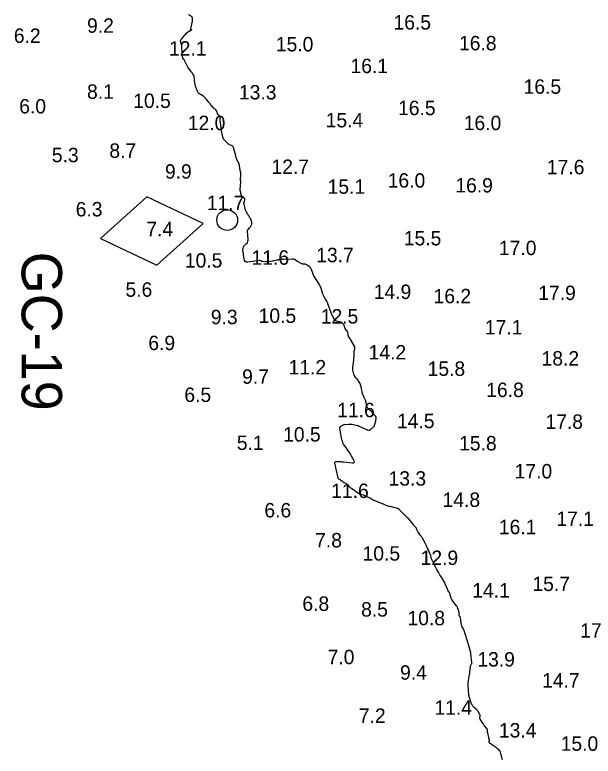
# Model space of a CAD drawing. Extents: x 815352 to 820877, y 582403 to 597439.
# Drawn here: x 819576.6 to 819777.2, y 593041.8 to 593298.9 of the extents above; entities that cross this region are included whole.
import ezdxf

# ---------------------------------------------------------------- set-up
doc = ezdxf.new("R2010")
doc.units = 0
for name, color, linetype in [('V-CHAN-NAID', 7, 'Continuous'), ('V-CONT-EL12', 7, 'Continuous'), ('V-TOPO-SOUN', 7, 'Continuous')]:
    doc.layers.add(name, color=color, linetype=linetype)

msp = doc.modelspace()

# ---------------------------------------------------------------- linework, layer by layer
at = {"layer": 'V-CHAN-NAID'}
msp.add_lwpolyline([(819641.95, 593226.5), (819622.41, 593235.79), (819606.32, 593221.33), (819625.86, 593212.04)], close=True, dxfattribs=at)
msp.add_circle((819650.26, 593227.71), 3.6, dxfattribs=at)
at = {"layer": 'V-CONT-EL12'}
for points in [[(819639.18, 593274.47), (819639.14, 593274.68), (819638.99, 593275.53), (819638.96, 593275.74), (819638.93, 593275.95), (819638.9, 593276.16), (819638.89, 593276.38), (819638.79, 593277.58), (819638.77, 593277.69), (819638.74, 593277.8), (819638.69, 593277.9), (819638.64, 593278), (819638.36, 593278.4), (819638.3, 593278.49), (819638.23, 593278.58), (819638.16, 593278.66), (819638.09, 593278.75), (819637.79, 593279.07), (819637.72, 593279.16), (819637.65, 593279.24), (819637.59, 593279.33), (819637.52, 593279.42), (819636.64, 593280.76), (819636.5, 593280.98), (819636.36, 593281.21), (819636.24, 593281.44), (819636.12, 593281.68), (819635.59, 593282.83), (819635.52, 593282.97), (819635.44, 593283.11), (819635.36, 593283.25), (819635.27, 593283.38), (819634.91, 593283.9), (819634.83, 593284.04), (819634.77, 593284.18), (819634.73, 593284.33), (819634.71, 593284.49), (819634.57, 593287.44), (819634.56, 593287.69), (819634.52, 593287.95), (819634.48, 593288.2), (819634.42, 593288.46), (819634.11, 593289.72), (819634.09, 593289.84), (819634.1, 593289.95), (819634.13, 593290.06), (819634.19, 593290.16), (819634.47, 593290.55), (819634.55, 593290.65), (819634.62, 593290.75), (819634.7, 593290.84), (819634.78, 593290.93), (819636.29, 593292.61), (819636.39, 593292.72), (819636.49, 593292.81), (819636.61, 593292.9), (819636.72, 593292.98), (819637.21, 593293.29), (819637.34, 593293.37), (819637.47, 593293.43), (819637.6, 593293.49), (819637.74, 593293.54), (819637.98, 593293.62), (819637.76, 593293.58), (819637.62, 593293.63), (819637.56, 593293.76), (819637.59, 593293.98), (819638.22, 593296.67), (819638.24, 593296.8), (819638.26, 593296.93), (819638.26, 593297.06), (819638.26, 593297.2), (819638.21, 593297.73), (819638.18, 593297.86), (819638.13, 593297.98), (819638.06, 593298.07), (819637.96, 593298.16), (819637.27, 593298.65), (819637.13, 593298.76), (819636.98, 593298.88), (819636.85, 593299)], [(819745.76, 593040.61), (819745.35, 593042.17), (819745.32, 593042.29), (819745.28, 593042.41), (819745.25, 593042.53), (819745.22, 593042.64), (819745.06, 593043.23), (819745.04, 593043.29), (819745.01, 593043.35), (819744.98, 593043.41), (819744.94, 593043.47), (819744.79, 593043.69), (819744.75, 593043.74), (819744.71, 593043.79), (819744.66, 593043.84), (819744.62, 593043.89), (819743.94, 593044.55), (819743.81, 593044.67), (819743.67, 593044.78), (819743.53, 593044.89), (819743.38, 593044.99), (819741.99, 593045.93), (819741.93, 593045.96), (819741.88, 593046), (819741.82, 593046.03), (819741.77, 593046.06), (819741.54, 593046.19), (819741.48, 593046.23), (819741.43, 593046.27), (819741.39, 593046.31), (819741.34, 593046.35), (819741.17, 593046.54), (819741.13, 593046.59), (819741.11, 593046.64), (819741.1, 593046.69), (819741.1, 593046.76), (819741.19, 593047.31), (819741.21, 593047.43), (819741.21, 593047.54), (819741.2, 593047.65), (819741.17, 593047.77), (819740.63, 593049.97), (819740.6, 593050.09), (819740.58, 593050.21), (819740.57, 593050.33), (819740.56, 593050.46), (819740.53, 593050.95), (819740.51, 593051.07), (819740.48, 593051.19), (819740.43, 593051.29), (819740.36, 593051.39), (819739.58, 593052.3), (819739.43, 593052.49), (819739.28, 593052.68), (819739.15, 593052.88), (819739.02, 593053.08), (819738.04, 593054.64), (819737.98, 593054.76), (819737.94, 593054.89), (819737.93, 593055.02), (819737.93, 593055.15), (819738.01, 593055.7), (819738.02, 593055.84), (819738.01, 593055.97), (819737.98, 593056.09), (819737.93, 593056.22), (819737.68, 593056.71), (819737.61, 593056.83), (819737.54, 593056.95), (819737.47, 593057.06), (819737.39, 593057.18), (819737.01, 593057.73), (819736.91, 593057.85), (819736.81, 593057.97), (819736.7, 593058.08), (819736.58, 593058.19), (819735.78, 593058.85), (819735.7, 593058.93), (819735.62, 593059.01), (819735.55, 593059.1), (819735.48, 593059.2), (819735.24, 593059.6), (819735.18, 593059.7), (819735.13, 593059.8), (819735.08, 593059.91), (819735.04, 593060.02), (819734.41, 593061.79), (819734.31, 593062.12), (819734.22, 593062.46), (819734.16, 593062.8), (819734.12, 593063.15), (819733.87, 593066.31), (819733.87, 593066.37), (819733.87, 593066.43), (819733.87, 593066.49), (819733.87, 593066.55), (819733.88, 593066.8), (819733.88, 593066.86), (819733.88, 593066.91), (819733.88, 593066.96), (819733.87, 593067.01), (819733.84, 593067.22), (819733.83, 593067.27), (819733.83, 593067.33), (819733.83, 593067.38), (819733.84, 593067.43), (819734.36, 593070.17), (819734.37, 593070.22), (819734.38, 593070.28), (819734.38, 593070.33), (819734.39, 593070.39), (819734.4, 593070.61), (819734.41, 593070.66), (819734.41, 593070.72), (819734.42, 593070.77), (819734.42, 593070.83), (819734.64, 593072.86), (819734.66, 593072.99), (819734.69, 593073.12), (819734.74, 593073.24), (819734.79, 593073.37), (819735.04, 593073.85), (819735.09, 593073.97), (819735.12, 593074.1), (819735.14, 593074.23), (819735.13, 593074.36), (819734.84, 593077.34), (819734.83, 593077.37), (819734.83, 593077.41), (819734.82, 593077.44), (819734.81, 593077.47), (819734.79, 593077.6), (819734.78, 593077.63), (819734.77, 593077.67), (819734.76, 593077.7), (819734.76, 593077.73), (819734.64, 593078.18), (819734.62, 593078.27), (819734.6, 593078.35), (819734.57, 593078.44), (819734.55, 593078.52), (819733.93, 593080.57), (819733.85, 593080.85), (819733.77, 593081.12), (819733.69, 593081.39), (819733.61, 593081.67), (819733.29, 593082.76), (819733.21, 593083.04), (819733.13, 593083.31), (819733.04, 593083.58), (819732.95, 593083.85), (819732.43, 593085.42), (819732.39, 593085.56), (819732.33, 593085.69), (819732.27, 593085.82), (819732.2, 593085.95), (819731.9, 593086.44), (819731.83, 593086.57), (819731.77, 593086.7), (819731.72, 593086.83), (819731.68, 593086.97), (819731.54, 593087.55), (819731.51, 593087.69), (819731.48, 593087.83), (819731.45, 593087.98), (819731.43, 593088.12), (819731.17, 593089.91), (819731.15, 593089.99), (819731.13, 593090.06), (819731.1, 593090.12), (819731.06, 593090.19), (819730.88, 593090.43), (819730.84, 593090.5), (819730.81, 593090.56), (819730.79, 593090.63), (819730.78, 593090.71), (819730.68, 593091.71), (819730.65, 593091.9), (819730.62, 593092.08), (819730.57, 593092.27), (819730.51, 593092.45), (819730.21, 593093.27), (819730.14, 593093.46), (819730.04, 593093.64), (819729.94, 593093.82), (819729.82, 593093.99), (819728.56, 593095.59), (819728.38, 593095.84), (819728.23, 593096.11), (819728.1, 593096.38), (819728, 593096.67), (819727.53, 593098.26), (819727.49, 593098.35), (819727.45, 593098.43), (819727.4, 593098.51), (819727.34, 593098.58), (819727.08, 593098.86), (819727.01, 593098.93), (819726.96, 593099.01), (819726.91, 593099.09), (819726.87, 593099.18), (819725.75, 593101.82), (819725.59, 593102.18), (819725.42, 593102.53), (819725.24, 593102.86), (819725.04, 593103.2), (819724.07, 593104.73), (819723.93, 593104.95), (819723.8, 593105.17), (819723.67, 593105.39), (819723.54, 593105.62), (819723.03, 593106.54), (819722.91, 593106.76), (819722.8, 593106.97), (819722.69, 593107.19), (819722.57, 593107.4), (819722.13, 593108.27), (819722.02, 593108.49), (819721.92, 593108.71), (819721.81, 593108.93), (819721.71, 593109.15), (819721.17, 593110.3), (819721.12, 593110.4), (819721.08, 593110.51), (819721.05, 593110.62), (819721.03, 593110.73), (819720.94, 593111.17), (819720.91, 593111.28), (819720.88, 593111.39), (819720.85, 593111.5), (819720.81, 593111.6), (819720.38, 593112.63), (819720.32, 593112.76), (819720.27, 593112.89), (819720.22, 593113.02), (819720.16, 593113.15), (819719.92, 593113.74), (819719.88, 593113.83), (819719.84, 593113.92), (819719.79, 593114), (819719.75, 593114.09), (819719.54, 593114.42), (819719.49, 593114.51), (819719.44, 593114.59), (819719.4, 593114.68), (819719.36, 593114.77), (819718.94, 593115.7), (819718.85, 593115.88), (819718.76, 593116.07), (819718.67, 593116.24), (819718.57, 593116.42), (819718.03, 593117.37), (819717.9, 593117.58), (819717.77, 593117.79), (819717.63, 593118), (819717.48, 593118.2), (819716.5, 593119.53), (819716.4, 593119.67), (819716.32, 593119.81), (819716.25, 593119.95), (819716.19, 593120.1), (819715.96, 593120.72), (819715.89, 593120.87), (819715.82, 593121.01), (819715.72, 593121.14), (819715.62, 593121.26), (819715.16, 593121.74), (819715.05, 593121.86), (819714.94, 593121.98), (819714.83, 593122.1), (819714.73, 593122.23), (819713.26, 593124.11), (819713.2, 593124.19), (819713.13, 593124.25), (819713.05, 593124.32), (819712.97, 593124.37), (819712.6, 593124.6), (819712.54, 593124.65), (819712.48, 593124.69), (819712.43, 593124.75), (819712.39, 593124.81), (819712.22, 593125.05), (819712.18, 593125.11), (819712.13, 593125.17), (819712.08, 593125.23), (819712.03, 593125.28), (819710.2, 593127.13), (819709.92, 593127.38), (819709.62, 593127.58), (819709.29, 593127.74), (819708.94, 593127.85), (819706.84, 593128.39), (819706.8, 593128.4), (819706.75, 593128.4), (819706.71, 593128.41), (819706.66, 593128.4), (819706.47, 593128.39), (819706.42, 593128.39), (819706.38, 593128.4), (819706.33, 593128.41), (819706.29, 593128.42), (819705.15, 593128.91), (819704.94, 593128.99), (819704.74, 593129.08), (819704.53, 593129.17), (819704.32, 593129.25), (819701.23, 593130.52), (819701.17, 593130.54), (819701.11, 593130.57), (819701.05, 593130.59), (819700.99, 593130.62), (819700.69, 593130.74), (819700.66, 593130.76), (819700.62, 593130.77), (819700.58, 593130.79), (819700.54, 593130.81), (819700.38, 593130.89), (819700.35, 593130.91), (819700.31, 593130.93), (819700.28, 593130.95), (819700.24, 593130.98), (819700.1, 593131.11), (819700.06, 593131.13), (819700.02, 593131.16), (819699.98, 593131.18), (819699.94, 593131.21), (819698.55, 593131.88), (819698.3, 593131.99), (819698.05, 593132.1), (819697.79, 593132.2), (819697.53, 593132.29), (819696.25, 593132.7), (819696.09, 593132.76), (819695.94, 593132.83), (819695.79, 593132.91), (819695.65, 593133), (819695.09, 593133.39), (819694.95, 593133.49), (819694.81, 593133.59), (819694.68, 593133.69), (819694.54, 593133.79), (819693.34, 593134.63), (819693.2, 593134.74), (819693.06, 593134.86), (819692.93, 593135), (819692.81, 593135.13), (819692.34, 593135.71), (819692.21, 593135.85), (819692.08, 593135.97), (819691.93, 593136.07), (819691.77, 593136.16), (819690.9, 593136.58), (819690.76, 593136.65), (819690.63, 593136.73), (819690.5, 593136.81), (819690.38, 593136.9), (819689.86, 593137.32), (819689.76, 593137.4), (819689.65, 593137.48), (819689.55, 593137.56), (819689.44, 593137.64), (819688.99, 593137.93), (819688.89, 593138.01), (819688.81, 593138.1), (819688.75, 593138.21), (819688.71, 593138.33), (819687.62, 593143.41), (819687.61, 593143.69), (819687.68, 593143.88), (819687.86, 593143.99), (819688.13, 593144.01), (819689.41, 593143.96), (819689.73, 593143.95), (819690.05, 593143.93), (819690.37, 593143.9), (819690.69, 593143.87), (819693.76, 593143.52), (819694.14, 593143.53), (819694.35, 593143.65), (819694.39, 593143.89), (819694.26, 593144.25), (819693.43, 593145.9), (819693.21, 593146.31), (819692.98, 593146.71), (819692.73, 593147.1), (819692.46, 593147.48), (819690.96, 593149.51), (819690.65, 593149.99), (819690.4, 593150.49), (819690.21, 593151.02), (819690.08, 593151.57), (819689.36, 593155.58), (819689.35, 593155.76), (819689.39, 593155.93), (819689.48, 593156.06), (819689.62, 593156.18), (819690.29, 593156.6), (819690.46, 593156.7), (819690.64, 593156.77), (819690.82, 593156.82), (819691.02, 593156.85), (819692.36, 593156.97), (819692.65, 593156.98), (819692.94, 593156.98), (819693.22, 593156.95), (819693.51, 593156.91), (819695.01, 593156.61), (819695.35, 593156.54), (819695.68, 593156.44), (819696.01, 593156.31), (819696.33, 593156.17), (819698.39, 593155.18), (819698.51, 593155.13), (819698.63, 593155.09), (819698.75, 593155.05), (819698.87, 593155.02), (819699.38, 593154.92), (819699.5, 593154.91), (819699.62, 593154.92), (819699.73, 593154.96), (819699.83, 593155.03), (819701.02, 593156.01), (819701.14, 593156.13), (819701.25, 593156.26), (819701.33, 593156.4), (819701.39, 593156.56), (819701.65, 593157.43), (819701.67, 593157.5), (819701.69, 593157.56), (819701.71, 593157.63), (819701.73, 593157.7), (819701.82, 593157.96), (819701.84, 593158.03), (819701.86, 593158.09), (819701.87, 593158.16), (819701.88, 593158.23), (819701.96, 593159.06), (819701.96, 593159.22), (819701.94, 593159.37), (819701.88, 593159.5), (819701.78, 593159.63), (819700.57, 593161.04), (819700.41, 593161.22), (819700.25, 593161.39), (819700.08, 593161.56), (819699.91, 593161.72), (819699.17, 593162.4), (819699.03, 593162.55), (819698.91, 593162.72), (819698.82, 593162.91), (819698.76, 593163.11), (819698.5, 593164.19), (819698.48, 593164.27), (819698.46, 593164.36), (819698.44, 593164.45), (819698.43, 593164.54), (819698.37, 593164.9), (819698.35, 593164.99), (819698.32, 593165.08), (819698.29, 593165.16), (819698.25, 593165.24), (819697.9, 593165.91), (819697.83, 593166.05), (819697.77, 593166.19), (819697.7, 593166.34), (819697.64, 593166.48), (819697.12, 593167.76), (819697.11, 593167.79), (819697.1, 593167.81), (819697.1, 593167.84), (819697.09, 593167.86), (819697.08, 593167.97), (819697.08, 593167.99), (819697.08, 593168.02), (819697.07, 593168.04), (819697.07, 593168.07), (819696.81, 593169.39), (819696.78, 593169.53), (819696.75, 593169.67), (819696.72, 593169.8), (819696.69, 593169.94), (819696.56, 593170.49), (819696.53, 593170.63), (819696.48, 593170.76), (819696.42, 593170.88), (819696.35, 593171.01), (819695.36, 593172.65), (819695.33, 593172.69), (819695.29, 593172.73), (819695.25, 593172.77), (819695.21, 593172.8), (819695.03, 593172.91), (819694.98, 593172.94), (819694.94, 593172.97), (819694.91, 593173.01), (819694.87, 593173.06), (819694.46, 593173.71), (819694.39, 593173.84), (819694.33, 593173.97), (819694.28, 593174.11), (819694.24, 593174.25), (819693.89, 593175.7), (819693.83, 593175.99), (819693.8, 593176.28), (819693.81, 593176.57), (819693.84, 593176.86), (819694.03, 593178.09), (819694.07, 593178.37), (819694.11, 593178.66), (819694.15, 593178.94), (819694.18, 593179.23), (819694.33, 593180.62), (819694.34, 593180.78), (819694.35, 593180.94), (819694.35, 593181.09), (819694.35, 593181.25), (819694.31, 593181.94), (819694.31, 593182.07), (819694.32, 593182.2), (819694.34, 593182.32), (819694.37, 593182.45), (819694.55, 593183.1), (819694.56, 593183.15), (819694.57, 593183.2), (819694.58, 593183.25), (819694.58, 593183.31), (819694.57, 593183.52), (819694.56, 593183.57), (819694.55, 593183.62), (819694.54, 593183.67), (819694.51, 593183.72), (819693.32, 593185.94), (819693.23, 593186.1), (819693.13, 593186.26), (819693.03, 593186.42), (819692.92, 593186.58), (819692.47, 593187.19), (819692.37, 593187.35), (819692.29, 593187.52), (819692.23, 593187.69), (819692.2, 593187.88), (819692.06, 593188.83), (819692.03, 593188.95), (819691.98, 593189.05), (819691.92, 593189.15), (819691.84, 593189.23), (819691.47, 593189.55), (819691.39, 593189.64), (819691.32, 593189.73), (819691.26, 593189.84), (819691.22, 593189.95), (819690.86, 593191.14), (819690.81, 593191.27), (819690.74, 593191.4), (819690.66, 593191.52), (819690.56, 593191.62), (819690.13, 593192.03), (819690.02, 593192.13), (819689.9, 593192.2), (819689.77, 593192.26), (819689.63, 593192.31), (819688.17, 593192.66), (819687.9, 593192.75), (819687.67, 593192.9), (819687.48, 593193.1), (819687.34, 593193.34), (819686.64, 593194.84), (819686.49, 593195.18), (819686.35, 593195.53), (819686.21, 593195.88), (819686.08, 593196.23), (819685.23, 593198.67), (819685.14, 593198.9), (819685.05, 593199.12), (819684.94, 593199.33), (819684.81, 593199.54), (819684.24, 593200.48), (819684.15, 593200.63), (819684.06, 593200.79), (819683.97, 593200.95), (819683.89, 593201.11), (819683.58, 593201.75), (819683.51, 593201.91), (819683.44, 593202.07), (819683.38, 593202.24), (819683.32, 593202.41), (819682.81, 593204.09), (819682.7, 593204.43), (819682.57, 593204.75), (819682.41, 593205.06), (819682.23, 593205.36), (819680.5, 593208.07), (819680.33, 593208.36), (819680.18, 593208.66), (819680.04, 593208.96), (819679.92, 593209.28), (819679.38, 593210.83), (819679.31, 593211), (819679.21, 593211.15), (819679.09, 593211.29), (819678.96, 593211.41), (819678.21, 593211.98), (819678.13, 593212.03), (819678.05, 593212.08), (819677.97, 593212.12), (819677.89, 593212.16), (819677.55, 593212.31), (819677.46, 593212.34), (819677.37, 593212.37), (819677.28, 593212.38), (819677.19, 593212.39), (819676.61, 593212.42), (819676.49, 593212.43), (819676.37, 593212.45), (819676.25, 593212.49), (819676.14, 593212.55), (819674.89, 593213.23), (819674.77, 593213.3), (819674.65, 593213.37), (819674.53, 593213.44), (819674.42, 593213.51), (819673.81, 593213.9), (819673.77, 593213.93), (819673.73, 593213.95), (819673.69, 593213.97), (819673.64, 593214), (819673.47, 593214.08), (819673.42, 593214.1), (819673.38, 593214.11), (819673.33, 593214.13), (819673.28, 593214.14), (819673.02, 593214.19), (819672.96, 593214.2), (819672.9, 593214.21), (819672.84, 593214.21), (819672.78, 593214.21), (819669.78, 593214.09), (819669.64, 593214.08), (819669.49, 593214.08), (819669.35, 593214.07), (819669.21, 593214.05), (819668.54, 593213.99), (819668.45, 593213.98), (819668.35, 593213.97), (819668.26, 593213.95), (819668.17, 593213.94), (819667.8, 593213.88), (819667.7, 593213.87), (819667.61, 593213.85), (819667.52, 593213.83), (819667.43, 593213.81), (819666.6, 593213.61), (819666.43, 593213.57), (819666.27, 593213.54), (819666.1, 593213.51), (819665.93, 593213.49), (819664.41, 593213.29), (819664.21, 593213.27), (819664.02, 593213.26), (819663.82, 593213.26), (819663.62, 593213.27), (819662.62, 593213.34), (819662.52, 593213.35), (819662.42, 593213.37), (819662.32, 593213.39), (819662.22, 593213.43), (819661.84, 593213.59), (819661.75, 593213.63), (819661.65, 593213.65), (819661.55, 593213.66), (819661.45, 593213.65), (819657.41, 593213.12), (819656.88, 593213.13), (819656.49, 593213.3), (819656.23, 593213.64), (819656.1, 593214.15), (819655.73, 593217.48), (819655.72, 593217.59), (819655.72, 593217.7), (819655.74, 593217.8), (819655.76, 593217.91), (819655.87, 593218.34), (819655.91, 593218.44), (819655.95, 593218.54), (819656.01, 593218.63), (819656.08, 593218.72), (819656.72, 593219.38), (819656.77, 593219.43), (819656.83, 593219.47), (819656.88, 593219.51), (819656.95, 593219.55), (819657.2, 593219.68), (819657.25, 593219.71), (819657.3, 593219.76), (819657.33, 593219.81), (819657.35, 593219.88), (819657.46, 593220.48), (819657.48, 593220.61), (819657.49, 593220.73), (819657.49, 593220.86), (819657.49, 593220.98), (819657.3, 593223.88), (819657.31, 593224.05), (819657.35, 593224.21), (819657.42, 593224.35), (819657.53, 593224.48), (819658.02, 593224.99), (819658.13, 593225.12), (819658.24, 593225.26), (819658.33, 593225.4), (819658.41, 593225.56), (819658.75, 593226.3), (819658.81, 593226.48), (819658.84, 593226.65), (819658.83, 593226.84), (819658.8, 593227.02), (819658.5, 593228.03), (819658.48, 593228.08), (819658.46, 593228.12), (819658.43, 593228.17), (819658.4, 593228.2), (819658.26, 593228.35), (819658.23, 593228.39), (819658.2, 593228.43), (819658.17, 593228.47), (819658.14, 593228.51), (819657.74, 593229.13), (819657.66, 593229.25), (819657.59, 593229.37), (819657.52, 593229.49), (819657.45, 593229.61), (819656.82, 593230.73), (819656.71, 593230.96), (819656.6, 593231.19), (819656.52, 593231.44), (819656.45, 593231.69), (819656.1, 593233.23), (819656.07, 593233.42), (819656.06, 593233.61), (819656.08, 593233.79), (819656.12, 593233.98), (819656.33, 593234.73), (819656.36, 593234.91), (819656.34, 593235.07), (819656.27, 593235.22), (819656.14, 593235.35), (819655.45, 593235.92), (819655.34, 593236.03), (819655.24, 593236.16), (819655.17, 593236.31), (819655.13, 593236.46), (819654.96, 593237.27), (819654.94, 593237.36), (819654.92, 593237.45), (819654.9, 593237.54), (819654.88, 593237.63), (819654.79, 593237.99), (819654.78, 593238.08), (819654.77, 593238.17), (819654.76, 593238.26), (819654.77, 593238.36), (819655, 593240.81), (819655.01, 593240.9), (819655, 593240.98), (819655, 593241.06), (819654.98, 593241.14), (819654.92, 593241.47), (819654.9, 593241.56), (819654.9, 593241.64), (819654.89, 593241.72), (819654.9, 593241.81), (819655, 593243.26), (819655.01, 593243.47), (819655, 593243.68), (819654.98, 593243.89), (819654.95, 593244.09), (819654.78, 593244.95), (819654.75, 593245.14), (819654.72, 593245.34), (819654.69, 593245.53), (819654.66, 593245.73), (819654.57, 593246.51), (819654.54, 593246.7), (819654.49, 593246.89), (819654.43, 593247.08), (819654.36, 593247.26), (819653.66, 593248.71), (819653.52, 593249.02), (819653.4, 593249.33), (819653.29, 593249.65), (819653.2, 593249.97), (819652.43, 593252.91), (819652.36, 593253.1), (819652.25, 593253.26), (819652.11, 593253.39), (819651.93, 593253.49), (819651.14, 593253.82), (819650.94, 593253.91), (819650.76, 593254.02), (819650.6, 593254.15), (819650.44, 593254.29), (819649.31, 593255.44), (819649.09, 593255.7), (819648.92, 593255.98), (819648.79, 593256.28), (819648.7, 593256.6), (819648.4, 593258.16), (819648.33, 593258.53), (819648.27, 593258.9), (819648.22, 593259.28), (819648.17, 593259.65), (819647.82, 593262.4), (819647.81, 593262.51), (819647.8, 593262.63), (819647.8, 593262.74), (819647.81, 593262.86), (819647.84, 593263.32), (819647.83, 593263.43), (819647.8, 593263.54), (819647.75, 593263.63), (819647.68, 593263.71), (819647.09, 593264.27), (819647.01, 593264.36), (819646.94, 593264.45), (819646.89, 593264.56), (819646.85, 593264.67), (819646.73, 593265.18), (819646.7, 593265.28), (819646.66, 593265.37), (819646.62, 593265.46), (819646.57, 593265.55), (819646.34, 593265.9), (819646.28, 593265.98), (819646.21, 593266.06), (819646.14, 593266.13), (819646.06, 593266.19), (819645.68, 593266.45), (819645.59, 593266.51), (819645.51, 593266.58), (819645.43, 593266.66), (819645.36, 593266.74), (819644.72, 593267.54), (819644.64, 593267.63), (819644.56, 593267.73), (819644.48, 593267.82), (819644.41, 593267.92), (819644.09, 593268.29), (819644.01, 593268.38), (819643.93, 593268.48), (819643.85, 593268.57), (819643.77, 593268.67), (819643.1, 593269.5), (819643, 593269.62), (819642.9, 593269.74), (819642.8, 593269.85), (819642.7, 593269.97), (819642.28, 593270.43), (819642.17, 593270.54), (819642.06, 593270.64), (819641.94, 593270.73), (819641.81, 593270.82), (819640.63, 593271.49), (819640.41, 593271.65), (819640.22, 593271.83), (819640.07, 593272.04), (819639.95, 593272.29), (819639.36, 593273.86), (819639.29, 593274.06), (819639.23, 593274.27), (819639.18, 593274.47)]]:
    msp.add_lwpolyline(points, dxfattribs=at)

# ---------------------------------------------------------------- texts
at = {"layer": 'V-CHAN-NAID'}
msp.add_text('GC-19', height=14, rotation=270, dxfattribs=at).set_placement((819578.95, 593216.75))
at = {"layer": 'V-TOPO-SOUN'}
for s, p in [('16.5 ', (819707.96, 593293.78)), ('9.2', (819601.64, 593292.66)), ('6.2', (819576.24, 593289.15)), ('15.0 ', (819667.14, 593286.2)), ('16.8 ', (819730.69, 593286.56)), ('12.1 ', (819630.08, 593284.72)), ('16.1 ', (819693.04, 593278.65)), ('16.5 ', (819753.1, 593271.5)), ('8.1', (819601.64, 593269.76)), ('13.3 ', (819654.35, 593269.53)), ('10.5 ', (819617.67, 593266.58)), ('6.0', (819578.11, 593264.68)), ('16.5 ', (819709.53, 593264.09)), ('12.0 ', (819636.6, 593258.9)), ('15.4 ', (819684.43, 593259.86)), ('16.0 ', (819732.33, 593258.9)), ('5.3', (819589.43, 593247.78)), ('8.7', (819609.38, 593249.29)), ('9.9', (819628.67, 593242.07)), ('12.7 ', (819665.63, 593243.71)), ('17.6 ', (819761.18, 593243.58)), ('15.1 ', (819685.1, 593236.82)), ('16.0 ', (819705.95, 593238.96)), ('16.9 ', (819729.41, 593237.28)), ('6.3', (819597.7, 593228.98)), ('11.7 ', (819643.16, 593231.18)), ('7.4', (819622.21, 593222.13)), ('15.5 ', (819711.53, 593218.94)), ('17.0 ', (819744.53, 593215.56)), ('10.5 ', (819635.58, 593211.23)), ('11.6 ', (819658.72, 593212.22)), ('13.7 ', (819681.15, 593213.1)), ('5.6', (819614.97, 593201.13)), ('14.9 ', (819701.1, 593200.34)), ('16.2 ', (819721.87, 593198.87)), ('17.9 ', (819758.19, 593199.98)), ('9.3', (819644.58, 593191.61)), ('10.5 ', (819661.17, 593192.07)), ('12.5 ', (819682.73, 593191.84)), ('17.1 ', (819739.66, 593188.04)), ('6.9', (819622.9, 593182.62)), ('14.2 ', (819699.33, 593179.38)), ('18.2 ', (819759.33, 593177.28)), ('11.2 ', (819671.57, 593174.19)), ('15.8 ', (819719.8, 593173.7)), ('9.7', (819655.44, 593170.95)), ('16.8 ', (819740.14, 593166.35)), ('6.5', (819635.4, 593164.65)), ('11.6 ', (819688.45, 593159.36)), ('14.5 ', (819709.17, 593155.56)), ('17.8 ', (819760.68, 593155.33)), ('10.5 ', (819669.67, 593150.93)), ('5.1', (819653.61, 593148.01)), ('15.8 ', (819730.73, 593147.85)), ('17.0 ', (819749.98, 593138.14)), ('13.3 ', (819706.25, 593135.64)), ('11.6 ', (819686.35, 593131.35)), ('14.8 ', (819724.98, 593128.26)), ('6.6', (819663.16, 593124.62)), ('17.1 ', (819764.46, 593121.67)), ('16.1 ', (819744.51, 593118.81)), ('7.8', (819680.77, 593114.22)), ('10.5 ', (819697.23, 593109.63)), ('12.9 ', (819717.37, 593108.12)), ('15.7 ', (819756.15, 593099.09)), ('14.1 ', (819735.29, 593096.83)), ('6.8', (819676.34, 593092.21)), ('8.5', (819696.72, 593090.24)), ('10.8 ', (819712.81, 593087.22)), ('17.2 ', (819772.75, 593082.92)), ('7.0', (819685.1, 593073.73)), ('13.9 ', (819737.06, 593072.91)), ('9.4', (819710.23, 593068.35)), ('14.7 ', (819759.5, 593065.63)), ('11.4 ', (819722.16, 593056.18)), ('7.2', (819695.93, 593053.39)), ('13.4 ', (819744.54, 593048.31)), ('15.0 ', (819765.96, 593043.71))]:
    msp.add_text(s, height=5, dxfattribs=at).set_placement(p)

doc.saveas('drawing.dxf')
